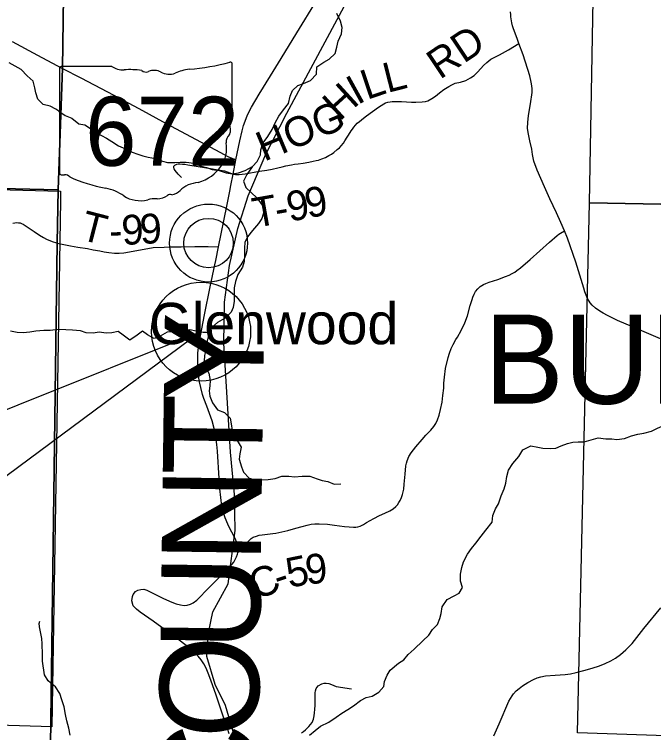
# Model space of a CAD drawing. Extents: x 0 to 34, y 0 to 22.
# Drawn here: x 5.288 to 6.508, y 16.577 to 17.948 of the extents above; entities that cross this region are included whole.
import ezdxf

# ---------------------------------------------------------------- set-up
doc = ezdxf.new("R2010")
doc.units = 0
for name, color, linetype in [('GM_X_Corporation', 7, 'Continuous'), ('GM_X_County_Road', 7, 'Continuous'), ('GM_X_County_Road_Text', 7, 'Continuous'), ('GM_X_County_Text', 7, 'Continuous'), ('GM_X_Minor_River', 7, 'Continuous'), ('GM_X_Rail_Line', 7, 'Continuous'), ('GM_X_State_Location', 7, 'Continuous'), ('GM_X_State_Route', 7, 'Continuous'), ('GM_X_State_Shield', 7, 'Continuous'), ('GM_X_Township_Road', 7, 'Continuous'), ('GM_X_Township_Road_Text', 7, 'Continuous'), ('GM_X_Township_Text', 7, 'Continuous'), ('GM_X_Unincorporated', 7, 'Continuous'), ('GM_X_Unincorporated_Location', 7, 'Continuous'), ('GM_X_Unincorporated_Text', 7, 'Continuous'), ('TX_P_1', 7, 'Continuous')]:
    doc.layers.add(name, color=color, linetype=linetype)

msp = doc.modelspace()

# ---------------------------------------------------------------- linework, layer by layer
at = {"layer": 'GM_X_Corporation'}
for points in [[(5.3543, 16.3597), (5.3699, 17.5116), (5.3717, 17.6123), (4.6401, 17.6298), (4.3705, 17.6391), (4.3669, 17.8198), (4.37, 17.9048), (4.3768, 18.4091), (4.3782, 18.6502), (4.377, 18.6713), (3.7035, 18.69), (3.3642, 18.7005), (3.3691, 19.5041), (3.3724, 19.7263), (3.3869, 20.7918), (3.3886, 20.9), (2.1, 20.9), (2.1, 15.6606)], [(5.3543, 16.3597), (5.3699, 17.5116), (5.3717, 17.6123), (5.3798, 17.8448), (5.3967, 19.0299), (5.4062, 19.5263), (5.4087, 19.6104), (5.6993, 19.6004), (6.6444, 19.5688), (7.0794, 19.5596), (7.3097, 19.5503), (7.9584, 19.5358), (7.9795, 19.5354), (8.4033, 19.5268)], [(8.4033, 19.5268), (7.9795, 19.5354), (7.9584, 19.5358), (7.3097, 19.5503), (7.0794, 19.5596), (6.6444, 19.5688), (5.6993, 19.6004), (5.4087, 19.6104), (5.4062, 19.5263), (5.3967, 19.0299), (5.3798, 17.8448), (5.3717, 17.6123), (5.3699, 17.5116), (5.3543, 16.3597)], [(8.4033, 19.5268), (7.9795, 19.5354), (7.9584, 19.5358), (7.3097, 19.5503), (7.0794, 19.5596), (6.6444, 19.5688), (5.6993, 19.6004), (5.4087, 19.6104), (5.4062, 19.5263), (5.3967, 19.0299), (5.3798, 17.8448), (5.3717, 17.6123), (5.3699, 17.5116), (5.3543, 16.3597)], [(3.3691, 19.5041), (3.3642, 18.7005), (3.7035, 18.69), (4.377, 18.6713), (4.3782, 18.6502), (4.3768, 18.4091), (4.37, 17.9048), (4.3669, 17.8198), (4.3705, 17.6391), (4.6401, 17.6298), (5.3717, 17.6123), (5.3798, 17.8448), (5.3967, 19.0299), (5.4062, 19.5263)], [(4.3565, 17.0622), (4.3675, 17.6365), (5.3765, 17.6099), (5.3761, 17.5925), (5.36, 16.5874), (4.3481, 16.6188), (4.352, 16.8239)]]:
    msp.add_lwpolyline(points, dxfattribs=at)
for points in [[(6.4033, 18.5738), (7.4054, 18.552), (7.375, 17.5696), (6.3854, 17.5878)], [(6.3854, 17.5878), (7.375, 17.5696), (7.3577, 16.5425), (6.3626, 16.5761)]]:
    msp.add_lwpolyline(points, close=True, dxfattribs=at)
at = {"layer": 'GM_X_County_Road'}
for points in [[(6.3379, 17.5342), (6.3312, 17.5501), (6.3226, 17.5684), (6.3101, 17.5955), (6.305, 17.6068), (6.2998, 17.6182), (6.2857, 17.6499), (6.2796, 17.6675), (6.2772, 17.6798), (6.2753, 17.6904), (6.2715, 17.706), (6.2685, 17.7219), (6.2676, 17.7305), (6.2678, 17.7413), (6.2694, 17.7544), (6.2728, 17.777), (6.276, 17.7985), (6.2762, 17.8054), (6.2754, 17.8114), (6.2744, 17.8183), (6.2715, 17.8302), (6.259, 17.87), (6.2508, 17.8916), (6.2475, 17.9013), (6.2404, 17.9199), (6.2387, 17.9257), (6.2372, 17.9315), (6.2357, 17.9426), (6.2353, 17.9468), (6.2351, 17.9523)], [(5.7143, 16.9197), (5.717, 16.9239), (5.7216, 16.9289), (5.7271, 16.9345), (5.7341, 16.9415), (5.7375, 16.9448), (5.7399, 16.9468), (5.7439, 16.9496), (5.7501, 16.9518), (5.7556, 16.9533), (5.7611, 16.9542), (5.771, 16.9553), (5.7814, 16.9564), (5.7869, 16.9574), (5.7929, 16.9585), (5.8098, 16.9626), (5.8251, 16.9668), (5.8374, 16.9703), (5.8466, 16.9725), (5.8543, 16.9743), (5.8616, 16.9751), (5.8695, 16.9754), (5.8857, 16.9745), (5.899, 16.9728), (5.918, 16.9703), (5.9272, 16.9692), (5.9354, 16.9686), (5.9399, 16.9687), (5.9435, 16.9694), (5.9479, 16.9708), (5.9542, 16.9739), (5.9602, 16.9774), (5.9742, 16.9854), (5.9849, 16.991), (5.9954, 16.9957), (6.0048, 16.9999), (6.011, 17.0036), (6.0158, 17.0079), (6.019, 17.0115), (6.022, 17.0158), (6.0245, 17.0198), (6.0271, 17.0252), (6.029, 17.031), (6.0311, 17.0414), (6.0321, 17.0511), (6.0336, 17.0702), (6.0353, 17.0855), (6.0362, 17.0907), (6.0375, 17.0956), (6.0411, 17.1034), (6.0453, 17.1105), (6.0542, 17.1219), (6.0662, 17.1363), (6.0735, 17.1444), (6.0827, 17.1538), (6.0888, 17.161), (6.0924, 17.1669), (6.0959, 17.1739), (6.0988, 17.1827), (6.1013, 17.1936), (6.1042, 17.2075), (6.1061, 17.2199), (6.1076, 17.2341), (6.108, 17.2438), (6.1087, 17.2551), (6.1109, 17.2718), (6.116, 17.2923), (6.1185, 17.3009), (6.122, 17.3095), (6.1256, 17.3173), (6.1308, 17.3269), (6.1337, 17.3317), (6.1405, 17.3441), (6.148, 17.3589), (6.1527, 17.3722), (6.1582, 17.3916), (6.16, 17.3977), (6.1615, 17.403), (6.1632, 17.408), (6.1653, 17.4135), (6.1683, 17.4186), (6.1724, 17.4237), (6.177, 17.4279), (6.1833, 17.4319), (6.188, 17.4338), (6.1942, 17.4361), (6.211, 17.4417), (6.2253, 17.4469), (6.2322, 17.4498), (6.2384, 17.453), (6.2431, 17.4557), (6.2468, 17.4584), (6.2537, 17.4637), (6.2725, 17.4799), (6.3091, 17.513), (6.3239, 17.5257), (6.3274, 17.528), (6.3306, 17.5301), (6.3379, 17.5342)], [(6.521, 17.3283), (6.4674, 17.3509), (6.4389, 17.3633), (6.4201, 17.3729), (6.4119, 17.3773), (6.4051, 17.3812), (6.3969, 17.3869), (6.3909, 17.3925), (6.3872, 17.397), (6.3816, 17.4053), (6.3768, 17.4181), (6.3746, 17.4248), (6.3721, 17.4332), (6.3595, 17.4744), (6.3434, 17.5201), (6.3379, 17.5342)]]:
    msp.add_lwpolyline(points, dxfattribs=at)
at = {"layer": 'GM_X_Minor_River'}
for points in [[(5.3731, 17.7628), (5.3852, 17.7545), (5.3977, 17.7496), (5.411, 17.7386), (5.4224, 17.7368), (5.4318, 17.7308), (5.4417, 17.7232), (5.4542, 17.716), (5.4641, 17.7112), (5.474, 17.7047), (5.4872, 17.6968), (5.5035, 17.6893), (5.513, 17.6848), (5.5236, 17.6807), (5.5335, 17.6777), (5.5433, 17.675), (5.5577, 17.6721), (5.5706, 17.6672), (5.5805, 17.6646), (5.5941, 17.6646), (5.6043, 17.6654), (5.6161, 17.6654), (5.6308, 17.6632), (5.6449, 17.6576), (5.6547, 17.655), (5.6657, 17.6516), (5.6793, 17.6494), (5.6926, 17.6449), (5.7043, 17.6434), (5.7157, 17.6449), (5.7286, 17.6495), (5.7429, 17.6572), (5.7516, 17.6667), (5.758, 17.6796), (5.7587, 17.6891), (5.7628, 17.702), (5.7719, 17.7145), (5.7802, 17.7278), (5.7858, 17.7403), (5.7926, 17.7532), (5.8017, 17.765), (5.8111, 17.7772), (5.8145, 17.7916), (5.819, 17.8022), (5.8292, 17.8117), (5.8401, 17.8156), (5.8534, 17.8213), (5.8647, 17.8335), (5.8654, 17.8475), (5.8786, 17.8566), (5.8888, 17.862), (5.9005, 17.8726), (5.9035, 17.8848), (5.9062, 17.8965), (5.9122, 17.9106), (5.914, 17.9227), (5.9102, 17.9345), (5.9033, 17.9492)], [(5.3731, 17.7628), (5.3671, 17.7667), (5.3564, 17.7724), (5.3431, 17.7757), (5.3328, 17.7855), (5.329, 17.7976), (5.327, 17.8075), (5.3239, 17.82), (5.3124, 17.8305), (5.301, 17.8422), (5.2899, 17.8485), (5.2785, 17.8549)], [(5.7419, 17.6566), (5.732, 17.6416), (5.7252, 17.6294), (5.7298, 17.6169), (5.74, 17.6075), (5.7514, 17.5969), (5.7613, 17.5833), (5.7644, 17.5708), (5.7602, 17.5579), (5.7542, 17.5484), (5.7425, 17.5351), (5.7331, 17.5229), (5.7282, 17.5123), (5.7275, 17.5021), (5.7271, 17.4888), (5.7264, 17.4759), (5.7238, 17.4653), (5.7144, 17.4509), (5.7099, 17.4376), (5.7076, 17.4254), (5.7073, 17.411), (5.7077, 17.4004), (5.7058, 17.3883), (5.7017, 17.3788), (5.6889, 17.367), (5.6756, 17.3594), (5.6651, 17.3499), (5.659, 17.3377), (5.6561, 17.3237), (5.6542, 17.3093), (5.6512, 17.2964), (5.6505, 17.2854), (5.6532, 17.2748), (5.6593, 17.2627), (5.6616, 17.2486), (5.6612, 17.2384), (5.6601, 17.2289), (5.6613, 17.2187), (5.6663, 17.2058), (5.6758, 17.193), (5.6894, 17.1873), (5.6997, 17.1771), (5.7027, 17.162), (5.7047, 17.1468), (5.7134, 17.1343), (5.721, 17.1215), (5.7184, 17.109), (5.7169, 17.0987), (5.7215, 17.084), (5.7257, 17.0734), (5.736, 17.062), (5.7477, 17.059), (5.7583, 17.0591), (5.7723, 17.0599), (5.7859, 17.0618), (5.7984, 17.066), (5.8117, 17.0661), (5.823, 17.0646), (5.8374, 17.0658), (5.8518, 17.0658), (5.8658, 17.0613), (5.8753, 17.0576), (5.8863, 17.0557), (5.8984, 17.0508), (5.9109, 17.0516)], [(5.3669, 17.3457), (5.3565, 17.3444), (5.3447, 17.3439), (5.3292, 17.343), (5.3174, 17.341), (5.3049, 17.3394), (5.2936, 17.3404), (5.2807, 17.3426)], [(5.6603, 17.3403), (5.6484, 17.3403), (5.6352, 17.3429), (5.6231, 17.3455), (5.6083, 17.3432), (5.5943, 17.3416), (5.5795, 17.3412), (5.5667, 17.3336), (5.5549, 17.329), (5.5424, 17.3358), (5.5329, 17.3426), (5.5227, 17.335), (5.5088, 17.3258), (5.4959, 17.3349), (5.4864, 17.342), (5.4743, 17.3397), (5.4633, 17.3389), (5.4497, 17.3408), (5.4383, 17.3392), (5.4254, 17.3395), (5.4144, 17.3437), (5.3993, 17.3448), (5.3864, 17.3455), (5.3739, 17.3458), (5.3669, 17.3457)], [(6.3117, 17.119), (6.3215, 17.1194), (6.3317, 17.1237), (6.3434, 17.1286), (6.3537, 17.1309), (6.3643, 17.1314), (6.3752, 17.1318), (6.4025, 17.1394), (6.4169, 17.1376), (6.4282, 17.1373), (6.4381, 17.1358), (6.4525, 17.1381), (6.4657, 17.1431), (6.4778, 17.1465), (6.4892, 17.1481), (6.5039, 17.1519), (6.5153, 17.1577), (6.5289, 17.1634), (6.5425, 17.1665), (6.555, 17.1775)], [(5.8514, 16.5719), (5.8619, 16.5807), (5.8725, 16.5887), (5.888, 16.5963), (5.902, 16.6062), (5.9133, 16.6138), (5.9247, 16.6207), (5.9353, 16.6279), (5.9489, 16.6382), (5.9594, 16.6439), (5.9708, 16.6463), (5.9837, 16.6535), (5.9931, 16.6649), (5.9946, 16.6744), (5.9998, 16.6862), (6.0055, 16.6957), (6.0213, 16.7094), (6.0312, 16.7155), (6.0399, 16.7257), (6.0508, 16.736), (6.0674, 16.7516), (6.0791, 16.7626), (6.0859, 16.7733), (6.0953, 16.7828), (6.1002, 16.7942), (6.1025, 16.804), (6.1047, 16.8166), (6.1141, 16.8306), (6.1274, 16.8375), (6.1372, 16.8428), (6.1432, 16.8538), (6.1394, 16.8656), (6.1394, 16.8788), (6.142, 16.8917), (6.145, 16.9027), (6.1529, 16.9172), (6.1604, 16.9282), (6.1687, 16.9381), (6.1789, 16.9518), (6.1876, 16.9632), (6.2, 16.9784), (6.2015, 16.9909), (6.206, 17.0038), (6.212, 17.0133), (6.2173, 17.0285), (6.2229, 17.0418), (6.2259, 17.0528), (6.2282, 17.0657), (6.2311, 17.0774), (6.2391, 17.0903), (6.2508, 17.1033), (6.2587, 17.1162), (6.2734, 17.1238), (6.2871, 17.1212), (6.2965, 17.1194), (6.3117, 17.119)], [(5.3359, 16.7788), (5.3354, 16.7853)], [(5.3355, 16.7849), (5.3366, 16.7891)], [(5.3569, 16.6716), (5.3527, 16.6756), (5.346, 16.6871), (5.342, 16.7128), (5.3416, 16.7257), (5.3414, 16.7462), (5.3406, 16.7565), (5.339, 16.7659), (5.3359, 16.7788)], [(5.3944, 16.5715), (5.3924, 16.5851), (5.3886, 16.5991), (5.3855, 16.6112), (5.3832, 16.6256), (5.379, 16.6393), (5.3752, 16.6514), (5.3668, 16.6639), (5.3569, 16.6716)]]:
    msp.add_lwpolyline(points, dxfattribs=at)
at = {"layer": 'GM_X_Rail_Line'}
msp.add_lwpolyline([(5.7067, 16.5743), (5.691, 16.6283), (5.6716, 16.6686), (5.6552, 16.722), (5.6585, 16.767), (5.6669, 16.8069), (5.6961, 16.8605), (5.7093, 16.9622), (5.7081, 17.0312), (5.7005, 17.1116), (5.6877, 17.3202), (5.689, 17.3981), (5.6984, 17.4681), (5.7143, 17.5387), (5.7344, 17.6014), (5.7682, 17.6805), (5.8084, 17.7591), (5.9312, 17.9893)], dxfattribs=at)
at = {"layer": 'GM_X_State_Route'}
msp.add_line((5.7058, 17.6427), (5.7111, 17.6698), dxfattribs=at)
for points in [[(5.7111, 17.6698), (5.7186, 17.7061), (5.7227, 17.7255), (5.7255, 17.7355), (5.7284, 17.7436), (5.7329, 17.7559), (5.7407, 17.7702), (5.7555, 17.7949), (5.7771, 17.83), (5.7923, 17.8552), (5.8322, 17.9203), (5.8596, 17.9649), (5.877, 17.9936), (5.8851, 18.0081), (5.888, 18.0139), (5.891, 18.0209), (5.8968, 18.0369), (5.9024, 18.0548), (5.913, 18.0899), (5.9252, 18.1309), (5.9429, 18.191)], [(5.2838, 17.8957), (5.3321, 17.8699), (5.3692, 17.8498), (5.38, 17.8442)], [(5.38, 17.8442), (5.415, 17.8263), (5.4658, 17.7996), (5.5258, 17.7676), (5.578, 17.7394), (5.6434, 17.7041), (5.6804, 17.6844), (5.6958, 17.6765), (5.7111, 17.6698)], [(5.6777, 17.5038), (5.6935, 17.5816), (5.6992, 17.6101), (5.7013, 17.6206), (5.7058, 17.6427)], [(5.698, 16.5745), (5.6952, 16.5842), (5.6907, 16.5963), (5.6724, 16.6497), (5.6637, 16.6747), (5.6595, 16.6867), (5.654, 16.6995), (5.6497, 16.7076), (5.6445, 16.7155), (5.639, 16.7226), (5.6317, 16.7301), (5.6237, 16.7374), (5.6137, 16.7448), (5.6027, 16.7529), (5.5529, 16.7892), (5.5284, 16.8068), (5.5214, 16.8122), (5.5148, 16.8189), (5.5125, 16.8279), (5.5133, 16.8361), (5.5152, 16.8405), (5.5192, 16.8457), (5.5238, 16.8485), (5.5293, 16.85), (5.5352, 16.8501), (5.5411, 16.8486), (5.5514, 16.8435), (5.5726, 16.8328), (5.5887, 16.8254), (5.5968, 16.8222), (5.6053, 16.8202), (5.6119, 16.8193), (5.6182, 16.82), (5.624, 16.8217), (5.6295, 16.8246), (5.6365, 16.8297), (5.66, 16.8534), (5.6995, 16.8932), (5.7068, 16.902), (5.7123, 16.9124), (5.7138, 16.917), (5.7143, 16.9197), (5.7138, 16.9356), (5.7108, 16.9438), (5.7068, 16.952), (5.6996, 16.9662), (5.6954, 16.9747), (5.6906, 16.9868), (5.6869, 16.9978), (5.6843, 17.0087), (5.682, 17.0253), (5.6805, 17.0419), (5.6791, 17.0617), (5.6756, 17.1139), (5.6747, 17.1265), (5.6728, 17.1408), (5.67, 17.1546), (5.6654, 17.1714), (5.6552, 17.1995), (5.6497, 17.2144), (5.6472, 17.2221), (5.6437, 17.2352), (5.641, 17.2487), (5.6389, 17.2646), (5.6382, 17.2815), (5.6384, 17.3013), (5.6401, 17.316), (5.6433, 17.3342), (5.6513, 17.3739), (5.6619, 17.4277), (5.6705, 17.4693), (5.6725, 17.478), (5.6777, 17.5038)]]:
    msp.add_lwpolyline(points, dxfattribs=at)
at = {"layer": 'GM_X_State_Shield'}
for p, q in [((5.7038, 17.7483), (5.7038, 17.853)), ((5.3742, 17.8446), (5.3742, 17.6444)), ((5.4739, 17.848), (5.3774, 17.848)), ((5.7037, 17.7483), (5.7038, 17.7483))]:
    msp.add_line(p, q, dxfattribs=at)
for centre, major_axis, start_param, end_param in [((5.5864, 18.1208), (0.3495, 0), 4.814394, 5.042369), ((5.7001, 17.8534), (0.00367, 0), 6.141152, 7.989035), ((5.3779, 17.845), (0.00382, 0), 1.712693, 3.28349), ((5.4969, 17.8712), (0.037, 0), 4.042523, 4.731795), ((5.5092, 17.7356), (0.133, 0), 1.404758, 1.657858), ((5.5394, 17.846), (0.0107, 0), 3.836095, 5.185415), ((5.5551, 17.8229), (0.0222, 0), 0.950623, 2.079405), ((5.5837, 17.8546), (0.0267, 0), 4.081561, 5.145723), ((5.6309, 17.7869), (0.0703, 0), 1.699011, 2.107814), ((5.7029, 17.7406), (0.00568, 0), 1.883978, 3.671073), ((5.6998, 17.7479), (0.00393, 0), 5.05454, 6.418171), ((5.6668, 17.7274), (0.0341, 0), 5.934695, 6.695948), ((5.7169, 17.7045), (0.0248, 0), 2.387724, 3.262537), ((5.6059, 17.6911), (0.0874, 0), 5.101752, 6.440018), ((5.378, 17.644), (0.00385, 0), 3.00124, 4.508301), ((5.3786, 17.6645), (0.0294, 0), 4.665946, 4.897461), ((5.3846, 17.6329), (0.0106, 0), 0.519207, 1.627899), ((5.5184, 17.8127), (0.2524, 0), 4.195997, 4.488961), ((5.6428, 17.5882), (0.0479, 0), 1.647645, 2.488434), ((5.4432, 17.5545), (0.079, 0), 0.823519, 1.323587), ((5.5853, 17.5975), (0.00752, 0), 1.147584, 2.315152), ((5.5821, 17.625), (0.0282, 0), 4.937069, 5.64225), ((5.5286, 17.6319), (0.0501, 0), 4.026481, 4.996735), ((5.5575, 17.5627), (0.0412, 0), 1.495662, 1.94098), ((5.5612, 17.6169), (0.0267, 0), 4.691044, 5.507374)]:
    msp.add_ellipse(centre, major_axis=major_axis, ratio=0.8, start_param=start_param, end_param=end_param, dxfattribs=at)
at = {"layer": 'GM_X_Township_Road'}
for points in [[(5.7058, 17.6427), (5.71, 17.6418), (5.7133, 17.6416), (5.7173, 17.6419), (5.7288, 17.6429), (5.756, 17.648), (5.7699, 17.6501), (5.7802, 17.6521), (5.7911, 17.6546), (5.7989, 17.6566), (5.8064, 17.6581), (5.8171, 17.6604), (5.823, 17.6616), (5.8297, 17.6624), (5.8391, 17.6636), (5.85, 17.6653), (5.8585, 17.6671), (5.8641, 17.6683), (5.8687, 17.6695), (5.8748, 17.6718), (5.8816, 17.6745), (5.8881, 17.6779), (5.8931, 17.6809), (5.8977, 17.684), (5.9043, 17.6893), (5.9085, 17.693), (5.912, 17.6965), (5.9161, 17.7015), (5.919, 17.706), (5.929, 17.7221), (5.931, 17.7255), (5.9331, 17.7284), (5.9358, 17.7325), (5.939, 17.7363), (5.9425, 17.7399), (5.9467, 17.7433), (5.9546, 17.7497), (5.9603, 17.7541), (5.9832, 17.7702), (5.9931, 17.777), (5.9966, 17.7785), (6.0006, 17.7799), (6.0055, 17.7807), (6.0093, 17.781), (6.0136, 17.7813), (6.0206, 17.7813), (6.027, 17.7812), (6.0363, 17.7804), (6.0462, 17.7797), (6.054, 17.7798), (6.0664, 17.7805), (6.0725, 17.7814), (6.0771, 17.7825), (6.0846, 17.7867), (6.0917, 17.7912), (6.0992, 17.7975), (6.1075, 17.8038), (6.117, 17.8098), (6.1232, 17.8133), (6.1292, 17.816), (6.1394, 17.818), (6.1496, 17.8216), (6.1587, 17.8265), (6.1656, 17.831), (6.172, 17.8371), (6.1785, 17.8444), (6.1836, 17.8499), (6.1897, 17.8557), (6.1974, 17.8617), (6.2136, 17.8704), (6.231, 17.8799), (6.2508, 17.8916)], [(5.6074, 17.6364), (5.601, 17.6427), (5.5951, 17.6492), (5.5929, 17.6524), (5.5922, 17.6552), (5.5928, 17.6575), (5.5946, 17.6598), (5.5985, 17.6615), (5.6007, 17.6621), (5.6039, 17.6622), (5.6092, 17.6619), (5.6133, 17.6616), (5.6189, 17.6606), (5.6548, 17.6546), (5.6849, 17.6496), (5.689, 17.6488), (5.6941, 17.6469), (5.7058, 17.6427)], [(5.6777, 17.5038), (5.6935, 17.5816), (5.6992, 17.6101), (5.7013, 17.6206), (5.7058, 17.6427)], [(5.2852, 17.5489), (5.2892, 17.5498), (5.293, 17.5501), (5.2963, 17.5499), (5.2995, 17.5493), (5.3017, 17.5486), (5.3048, 17.5468), (5.3257, 17.533), (5.3361, 17.5263), (5.3437, 17.5219), (5.3498, 17.5187), (5.3571, 17.5153), (5.3621, 17.5135), (5.3666, 17.512), (5.3701, 17.5111)], [(5.3701, 17.5111), (5.395, 17.5055), (5.4095, 17.5029), (5.4277, 17.5004), (5.4385, 17.4983), (5.4511, 17.496), (5.4598, 17.4943), (5.4684, 17.4928), (5.479, 17.4918), (5.4879, 17.4918), (5.4972, 17.4924), (5.5287, 17.4979), (5.5531, 17.5025), (5.5741, 17.5032), (5.5846, 17.5038), (5.6064, 17.5039), (5.6328, 17.5046), (5.6455, 17.5047), (5.6583, 17.5046), (5.6777, 17.5038)], [(6.203, 16.5702), (6.2135, 16.5933), (6.232, 16.6365), (6.2347, 16.6416), (6.2378, 16.6467), (6.2407, 16.6508), (6.2457, 16.6562), (6.2515, 16.6611), (6.2578, 16.6657), (6.2677, 16.6721), (6.279, 16.6779), (6.2859, 16.681), (6.2929, 16.6833), (6.3015, 16.6852), (6.3199, 16.6862), (6.339, 16.6874), (6.3492, 16.689), (6.36, 16.6911), (6.3751, 16.6951), (6.3905, 16.6999), (6.4046, 16.7043), (6.4157, 16.7084), (6.4264, 16.7138), (6.4351, 16.7188), (6.4448, 16.7258), (6.4551, 16.7348), (6.4669, 16.7469), (6.4893, 16.7752), (6.5216, 16.8149)], [(5.8359, 16.5759), (5.8397, 16.5789), (5.8435, 16.5821), (5.8469, 16.585), (5.85, 16.5882), (5.8534, 16.592), (5.8564, 16.5961), (5.858, 16.5991), (5.8593, 16.6023), (5.8605, 16.6085), (5.861, 16.6143), (5.8615, 16.6208), (5.8622, 16.6287), (5.8624, 16.6396), (5.8622, 16.6525), (5.863, 16.6564), (5.8643, 16.6609), (5.8679, 16.666), (5.8749, 16.6699), (5.8792, 16.671), (5.8831, 16.6712), (5.8882, 16.6704), (5.8936, 16.6682), (5.9023, 16.6648), (5.9315, 16.6603)]]:
    msp.add_lwpolyline(points, dxfattribs=at)
at = {"layer": 'GM_X_Unincorporated'}
for radius in [0.0744, 0.0472]:
    msp.add_circle((5.6587, 17.511), radius, dxfattribs=at)
at = {"layer": 'GM_X_Unincorporated_Location'}
msp.add_line((5.6587, 17.511), (5.6587, 17.511), dxfattribs=at)
at = {"layer": 'TX_P_1'}
msp.add_lwpolyline([(4.9455, 17.0622), (5.6445, 17.3419), (4.9455, 16.8239)], close=True, dxfattribs=at)
msp.add_circle((5.6445, 17.3419), 0.0945, dxfattribs=at)

# ---------------------------------------------------------------- texts
at = {"layer": 'GM_X_County_Road_Text'}
for s, rotation, p in [('9', 5.2261, (5.8455, 16.8593)), ('5', 11.5896, (5.8128, 16.8525)), ('C', 21.1349, (5.7495, 16.8292)), ('-', 17.9532, (5.7923, 16.8458))]:
    msp.add_text(s, height=0.0568, rotation=rotation, dxfattribs=at).set_placement(p)
at = {"layer": 'GM_X_County_Text'}
for s, rotation, p in [('Y', 89.2289, (5.7626, 17.2082)), ('T', 89.2286, (5.7607, 17.0666)), ('N', 89.2287, (5.7584, 16.8991)), ('U', 89.2287, (5.7562, 16.7316)), ('O', 89.2289, (5.7539, 16.5641)), ('C', 89.2288, (5.7519, 16.4099))]:
    msp.add_text(s, height=0.1894, rotation=rotation, dxfattribs=at).set_placement(p)
at = {"layer": 'GM_X_State_Location'}
for s in ['s', 'r']:
    msp.add_text(s, height=0.000189, dxfattribs=at).set_placement((5.5353, 17.7312))
msp.add_text('672', height=0.000189, rotation=0, dxfattribs=at).set_placement((5.4684, 17.7174))
at = {"layer": 'GM_X_State_Shield'}
msp.add_text('672', height=0.13184, dxfattribs=at).set_placement((5.4232, 17.6585))
at = {"layer": 'GM_X_Township_Road_Text'}
for s, height, rotation, p in [('RD', 0.05682, 33.8254, (6.1001, 17.8223)), ('L', 0.0568, 14.2857, (6, 17.7974)), ('L', 0.0568, 18.6843, (5.9609, 17.7841)), ('I', 0.0568, 28.9325, (5.9429, 17.7739)), ('H', 0.0568, 42.3871, (5.9089, 17.7423)), ('HOG', 0.05682, 22.6437, (5.7648, 17.6661)), ('9', 0.0568, 11.1034, (5.8483, 17.5581)), ('T', 0.0568, 10.0196, (5.7479, 17.5401)), ('9', 0.0568, 10.2711, (5.813, 17.5516)), ('-', 0.0568, 10.0564, (5.7898, 17.5475)), ('T', 0.0568, 345.5466, (5.411, 17.5186)), ('9', 0.0568, 3.2452, (5.4942, 17.5071)), ('9', 0.0568, 3.2506, (5.5289, 17.509)), ('-', 0.0568, 2.1618, (5.4699, 17.5061))]:
    msp.add_text(s, height=height, rotation=rotation, dxfattribs=at).set_placement(p)
at = {"layer": 'GM_X_Township_Text'}
msp.add_text('BUFFALO', height=0.17045, rotation=0, dxfattribs=at).set_placement((6.1846, 17.2042))
at = {"layer": 'GM_X_Unincorporated_Text'}
msp.add_text('Glenwood', height=0.07898, rotation=0, dxfattribs=at).set_placement((5.5451, 17.3179))

doc.saveas('drawing.dxf')
